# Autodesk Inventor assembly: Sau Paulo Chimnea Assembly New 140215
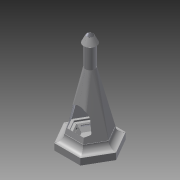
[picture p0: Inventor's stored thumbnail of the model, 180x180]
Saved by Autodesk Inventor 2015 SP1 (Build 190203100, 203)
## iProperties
Created: 2014-12
Part Number: Sau Paulo Chimnea Assembly New 140215
Document SubType Name: Assembly
Designer: rsheridan
Author: rsheridan
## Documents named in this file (3)
- \\psf\Home\Documents\Inventor\Sau Paulo Chimnea\Sau Paulo Chimnea Assembly New 140215.iam
- \\psf\Home\Documents\Inventor\Sau Paulo Chimnea\Upper_Assy_New.iam
- \\psf\Home\Documents\Inventor\Sau Paulo Chimnea\Base Assembly New.iam
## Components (2 placed, 2 different names)
1. Upper_Assy_New:1 [sub-assembly] — Mate:1, Mate:2, Mate:3
2. Base Assembly New:1 [sub-assembly] — Mate:1, Mate:2, Mate:3
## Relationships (3: Mate 3)
- Mate:1: Upper_Assy_New:1 ↔ Base Assembly New:1
- Mate:2: Upper_Assy_New:1 ↔ Base Assembly New:1
- Mate:3: Upper_Assy_New:1 ↔ Base Assembly New:1
